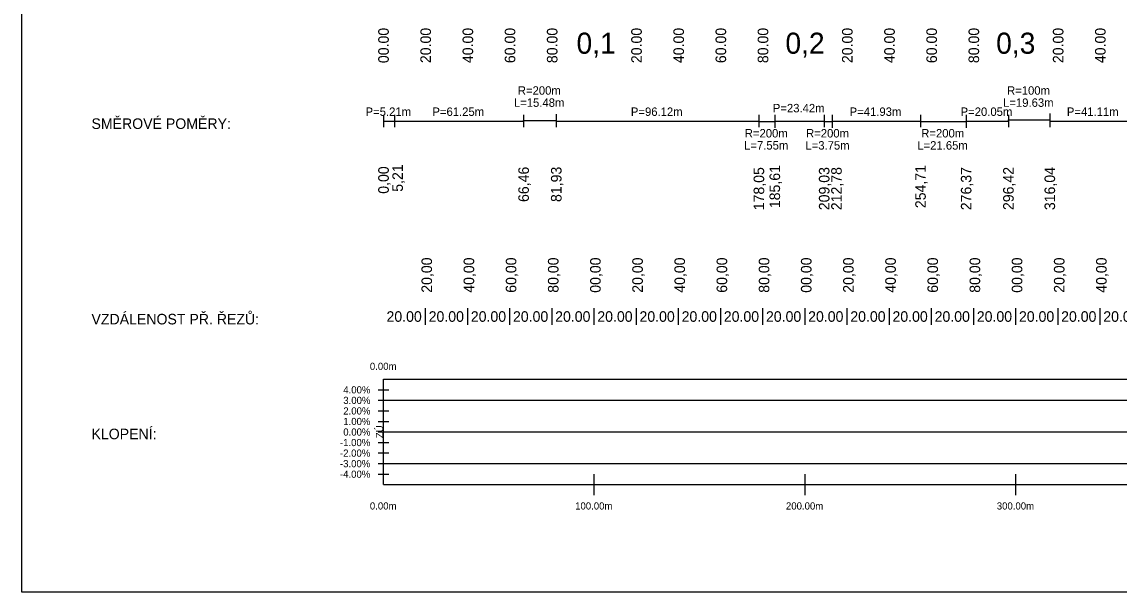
# Model space of a CAD drawing. Extents: x -603528 to -602138, y -1111983 to -1111218.
# Drawn here: x -603528 to -603007, y -1111983 to -1111712 of the extents above; entities that cross this region are included whole.
import ezdxf

# ---------------------------------------------------------------- set-up
doc = ezdxf.new("R2010")
doc.units = 0
for name, color, linetype in [('_křivky z hran', 7, 'Continuous'), ('_netisk', 7, 'Continuous'), ('C3D_Klopeni', 7, 'Continuous'), ('C3D_ZPP', 7, 'Continuous'), ('C3D_ZPP-Prouzky', 7, 'Continuous'), ('Default', 7, 'Continuous')]:
    doc.layers.add(name, color=color, linetype=linetype)

# ---------------------------------------------------------------- blocks, each defined once
blk = doc.blocks.new('AeccTickLine')
at = {"layer": 'Default'}
blk.add_line((0, 1), (0, -1), dxfattribs=at)

msp = doc.modelspace()

# ---------------------------------------------------------------- linework, layer by layer
at = {"layer": '_netisk'}
msp.add_lwpolyline([(-603527.56, -1111262.74), (-602137.56, -1111262.74), (-602137.56, -1111982.74), (-603527.56, -1111982.74)], close=True, dxfattribs=at)
at = {"layer": 'C3D_Klopeni'}
for p, q in [((-603356.07, -1111931.8), (-603356.07, -1111881.8)), ((-603356.07, -1111881.8), (-602584.81, -1111881.8)), ((-603356.07, -1111931.8), (-603356.07, -1111881.8)), ((-603358.57, -1111886.8), (-603353.57, -1111886.8)), ((-603358.57, -1111891.8), (-603353.57, -1111891.8)), ((-603356.07, -1111891.8), (-602594.8, -1111891.8)), ((-603358.57, -1111896.8), (-603353.57, -1111896.8)), ((-603358.57, -1111901.8), (-603353.57, -1111901.8)), ((-603358.57, -1111906.8), (-603353.57, -1111906.8)), ((-603356.07, -1111906.8), (-602584.81, -1111906.8)), ((-603358.57, -1111911.8), (-603353.57, -1111911.8)), ((-603358.57, -1111916.8), (-603353.57, -1111916.8)), ((-603358.57, -1111921.8), (-603353.57, -1111921.8)), ((-603356.07, -1111921.8), (-602594.8, -1111921.8)), ((-603358.57, -1111926.8), (-603353.57, -1111926.8)), ((-603256.07, -1111936.8), (-603256.07, -1111926.8)), ((-603156.07, -1111936.8), (-603156.07, -1111926.8)), ((-603056.07, -1111936.8), (-603056.07, -1111926.8)), ((-603356.07, -1111931.8), (-602584.81, -1111931.8))]:
    msp.add_line(p, q, dxfattribs=at)
at = {"layer": 'C3D_ZPP'}
for p, q in [((-603059.66, -1111759.4), (-603059.66, -1111758.86)), ((-603059.66, -1111758.86), (-603040.03, -1111758.86)), ((-603040.03, -1111758.86), (-603040.03, -1111759.4)), ((-603356.07, -1111759.4), (-603289.62, -1111759.4)), ((-603289.62, -1111759.4), (-603289.62, -1111759.13)), ((-603289.62, -1111759.13), (-603274.14, -1111759.13)), ((-603274.14, -1111759.13), (-603274.14, -1111759.4)), ((-603274.14, -1111759.4), (-603178.02, -1111759.4)), ((-603178.02, -1111759.4), (-603178.02, -1111759.67)), ((-603178.02, -1111759.67), (-603170.47, -1111759.67)), ((-603170.47, -1111759.67), (-603170.47, -1111759.4)), ((-603170.47, -1111759.4), (-603147.05, -1111759.4)), ((-603147.05, -1111759.4), (-603147.05, -1111759.67)), ((-603147.05, -1111759.67), (-603143.3, -1111759.67)), ((-603143.3, -1111759.67), (-603143.3, -1111759.4)), ((-603143.3, -1111759.4), (-603101.36, -1111759.4)), ((-603101.36, -1111759.4), (-603101.36, -1111759.67)), ((-603101.36, -1111759.67), (-603079.71, -1111759.67)), ((-603079.71, -1111759.67), (-603079.71, -1111759.4)), ((-603079.71, -1111759.4), (-603059.66, -1111759.4)), ((-603040.03, -1111759.4), (-602998.92, -1111759.4))]:
    msp.add_line(p, q, dxfattribs=at)
at = {"layer": 'C3D_ZPP-Prouzky'}
for p, q in [((-603336.07, -1111856.08), (-603336.07, -1111848.08)), ((-603316.07, -1111856.08), (-603316.07, -1111848.08)), ((-603296.07, -1111856.08), (-603296.07, -1111848.08)), ((-603276.07, -1111856.08), (-603276.07, -1111848.08)), ((-603256.07, -1111856.08), (-603256.07, -1111848.08)), ((-603236.07, -1111856.08), (-603236.07, -1111848.08)), ((-603216.07, -1111856.08), (-603216.07, -1111848.08)), ((-603196.07, -1111856.08), (-603196.07, -1111848.08)), ((-603176.07, -1111856.08), (-603176.07, -1111848.08)), ((-603156.07, -1111856.08), (-603156.07, -1111848.08)), ((-603136.07, -1111856.08), (-603136.07, -1111848.08)), ((-603116.07, -1111856.08), (-603116.07, -1111848.08)), ((-603096.07, -1111856.08), (-603096.07, -1111848.08)), ((-603076.07, -1111856.08), (-603076.07, -1111848.08)), ((-603056.07, -1111856.08), (-603056.07, -1111848.08)), ((-603036.07, -1111856.08), (-603036.07, -1111848.08)), ((-603016.07, -1111856.08), (-603016.07, -1111848.08))]:
    msp.add_line(p, q, dxfattribs=at)

# ---------------------------------------------------------------- block references
at = {"layer": '_křivky z hran', "xscale": 3, "yscale": 3}
for p in [(-603356.07, -1111759.4), (-603350.86, -1111759.4), (-603289.62, -1111759.4), (-603274.14, -1111759.13), (-603274.14, -1111759.4), (-603178.02, -1111759.4), (-603170.47, -1111759.4), (-603170.47, -1111759.67), (-603147.05, -1111759.4), (-603143.3, -1111759.4), (-603143.3, -1111759.67), (-603101.36, -1111759.4), (-603079.71, -1111759.4), (-603079.71, -1111759.67), (-603059.66, -1111759.4), (-603040.03, -1111758.86), (-603040.03, -1111759.4)]:
    msp.add_blockref('AeccTickLine', p, dxfattribs=at)

# ---------------------------------------------------------------- texts
at = {"layer": 'C3D_Klopeni'}
for s, p in [('0.00m', (-603362.52, -1111877.42)), ('0.00m', (-603362.52, -1111877.42)), ('4.00%', (-603375.14, -1111888.56)), ('3.00%', (-603375.14, -1111893.56)), ('2.00%', (-603375.14, -1111898.56)), ('1.00%', (-603375.14, -1111903.56)), ('0.00%', (-603375.14, -1111908.56)), ('0.00%', (-603375.14, -1111908.56)), ('-1.00%', (-603376.72, -1111913.56)), ('-2.00%', (-603376.72, -1111918.56)), ('-3.00%', (-603376.72, -1111923.56)), ('-4.00%', (-603376.72, -1111928.56)), ('0.00m', (-603362.52, -1111943.62)), ('100.00m', (-603265.16, -1111943.62)), ('200.00m', (-603165.16, -1111943.62)), ('300.00m', (-603065.16, -1111943.62))]:
    msp.add_text(s, height=3.4, dxfattribs=at).set_placement(p)
msp.add_text('ZÚ', height=3.4, rotation=90, dxfattribs=at).set_placement((-603356.21, -1111909.78))
at = {"layer": 'C3D_ZPP'}
for s, p in [('SMĚROVÉ POMĚRY:', (-603494.57, -1111763.16)), ('VZDÁLENOST PŘ. ŘEZŮ:', (-603494.57, -1111855.84)), ('KLOPENÍ:', (-603494.57, -1111910.28))]:
    msp.add_text(s, height=5, dxfattribs=at).set_placement(p)
at = {"layer": 'C3D_ZPP-Prouzky'}
for s, p in [('00.00', (-603353.55, -1111731.96)), ('20.00', (-603333.55, -1111731.96)), ('40.00', (-603313.55, -1111731.96)), ('60.00', (-603293.55, -1111731.96)), ('80.00', (-603273.55, -1111731.96)), ('20.00', (-603233.55, -1111731.96)), ('40.00', (-603213.55, -1111731.96)), ('60.00', (-603193.55, -1111731.96)), ('80.00', (-603173.55, -1111731.96)), ('20.00', (-603133.55, -1111731.96)), ('40.00', (-603113.55, -1111731.96)), ('60.00', (-603093.55, -1111731.96)), ('80.00', (-603073.55, -1111731.96)), ('20.00', (-603033.55, -1111731.96)), ('40.00', (-603013.55, -1111731.96)), ('0,00', (-603353.55, -1111793.9)), ('5,21', (-603346.86, -1111792.95)), ('66,46', (-603287.1, -1111797.8)), ('81,93', (-603271.62, -1111797.8)), ('178,05', (-603175.5, -1111801.72)), ('185,61', (-603167.95, -1111800.72)), ('209,03', (-603144.53, -1111801.69)), ('212,78', (-603138.7, -1111801.69)), ('254,71', (-603098.84, -1111800.72)), ('276,37', (-603077.19, -1111801.69)), ('296,42', (-603057.14, -1111801.63)), ('316,04', (-603037.51, -1111801.66)), ('20,00', (-603333.05, -1111840.84)), ('40,00', (-603313.05, -1111840.84)), ('60,00', (-603293.05, -1111840.84)), ('80,00', (-603273.05, -1111840.84)), ('00,00', (-603253.05, -1111840.84)), ('20,00', (-603233.05, -1111840.84)), ('40,00', (-603213.05, -1111840.84)), ('60,00', (-603193.05, -1111840.84)), ('80,00', (-603173.05, -1111840.84)), ('00,00', (-603153.05, -1111840.84)), ('20,00', (-603133.05, -1111840.84)), ('40,00', (-603113.05, -1111840.84)), ('60,00', (-603093.05, -1111840.84)), ('80,00', (-603073.05, -1111840.84)), ('00,00', (-603053.05, -1111840.84)), ('20,00', (-603033.05, -1111840.84)), ('40,00', (-603013.05, -1111840.84))]:
    msp.add_text(s, height=5, rotation=90, dxfattribs=at).set_placement(p)
for s, height, p in [('0,1', 10, (-603264.5, -1111727.51)), ('0,2', 10, (-603165.41, -1111727.51)), ('0,3', 10, (-603065.46, -1111727.51)), ('R=200m', 4, (-603292.34, -1111746.93)), ('R=100m', 4, (-603060.3, -1111746.93)), ('P=5.21m', 4, (-603364.55, -1111756.98)), ('P=61.25m', 4, (-603332.87, -1111756.98)), ('L=15.48m', 4, (-603294.2, -1111752.68)), ('P=96.12m', 4, (-603238.72, -1111756.98)), ('P=23.42m', 4, (-603171.39, -1111755.29)), ('P=41.93m', 4, (-603134.96, -1111756.98)), ('P=20.05m', 4, (-603082.32, -1111756.98)), ('L=19.63m', 4, (-603062.17, -1111752.68)), ('P=41.11m', 4, (-603031.9, -1111756.98)), ('R=200m', 4, (-603184.7, -1111767.21)), ('R=200m', 4, (-603155.63, -1111767.21)), ('R=200m', 4, (-603100.99, -1111767.21)), ('L=7.55m', 4, (-603185.01, -1111772.94)), ('L=3.75m', 4, (-603155.94, -1111772.96)), ('L=21.65m', 4, (-603102.86, -1111772.96)), ('20.00', 5, (-603354.64, -1111854.6)), ('20.00', 5, (-603334.64, -1111854.6)), ('20.00', 5, (-603314.64, -1111854.6)), ('20.00', 5, (-603294.64, -1111854.6)), ('20.00', 5, (-603274.64, -1111854.6)), ('20.00', 5, (-603254.64, -1111854.6)), ('20.00', 5, (-603234.64, -1111854.6)), ('20.00', 5, (-603214.64, -1111854.6)), ('20.00', 5, (-603194.64, -1111854.6)), ('20.00', 5, (-603174.64, -1111854.6)), ('20.00', 5, (-603154.64, -1111854.6)), ('20.00', 5, (-603134.64, -1111854.6)), ('20.00', 5, (-603114.64, -1111854.6)), ('20.00', 5, (-603094.64, -1111854.6)), ('20.00', 5, (-603074.64, -1111854.6)), ('20.00', 5, (-603054.64, -1111854.6)), ('20.00', 5, (-603034.64, -1111854.6)), ('20.00', 5, (-603014.64, -1111854.6))]:
    msp.add_text(s, height=height, dxfattribs=at).set_placement(p)

doc.saveas('drawing.dxf')
